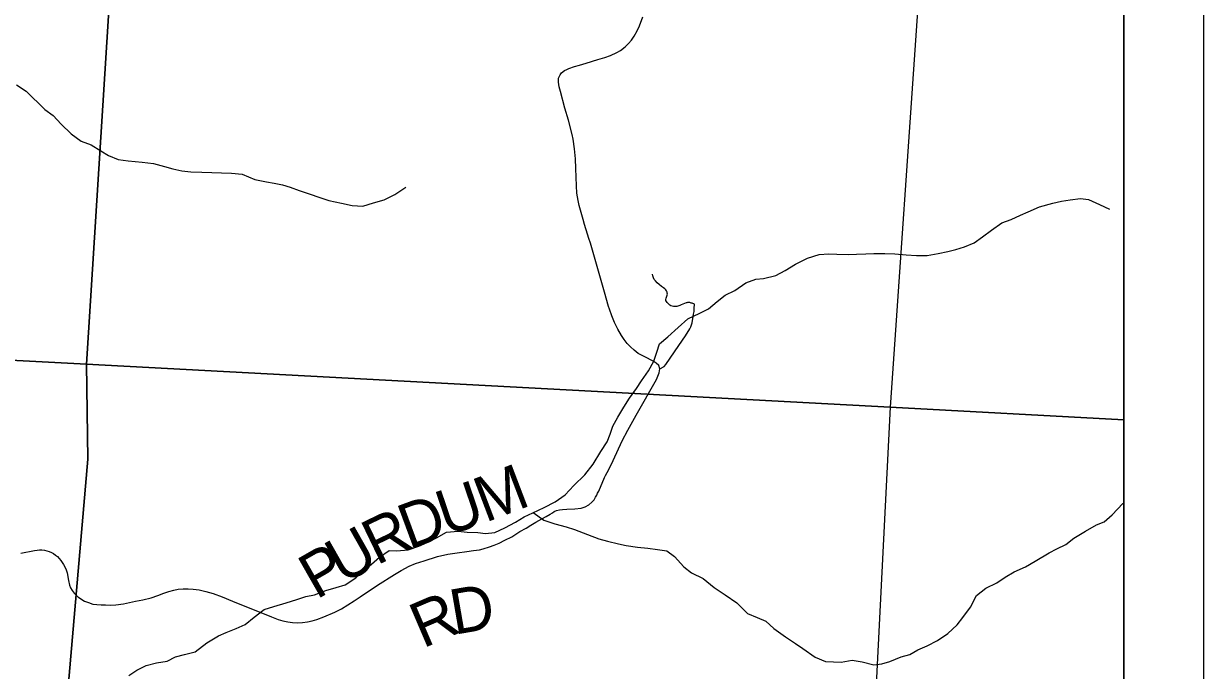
# Model space of a CAD drawing. Extents: x 0 to 34, y 0 to 22.
# Drawn here: x 7.515 to 9, y 19.373 to 20.186 of the extents above; entities that cross this region are included whole.
import ezdxf

# ---------------------------------------------------------------- set-up
doc = ezdxf.new("R2010")
doc.units = 0
for name, color, linetype in [('GM_X_Corporation', 7, 'Continuous'), ('GM_X_Minor_River', 7, 'Continuous'), ('GM_X_Township_Road', 7, 'Continuous'), ('GM_X_Township_Road_Text', 7, 'Continuous'), ('SH_Data', 7, 'Continuous')]:
    doc.layers.add(name, color=color, linetype=linetype)

msp = doc.modelspace()

# ---------------------------------------------------------------- linework, layer by layer
at = {"layer": 'GM_X_Corporation'}
for points in [[(8.9, 18.631), (8.9, 20.9), (3.6477, 20.9), (3.6464, 20.8827), (3.5665, 19.797), (3.566, 19.7906), (3.507, 18.9883), (4.2931, 18.935), (4.421, 18.9263), (4.4362, 18.9253), (5.6003, 18.8464), (6.4706, 18.7873), (6.895, 18.7585), (7.0255, 18.7497), (7.0714, 18.7466), (7.0845, 18.7457), (7.389, 18.725), (7.8088, 18.6965), (7.8353, 18.6952)], [(6.6504, 20.8365), (7.0809, 20.8104), (7.4778, 20.7864), (7.6585, 20.7741), (7.5941, 19.7583), (6.5798, 19.8114)], [(7.6585, 20.7741), (7.6694, 20.7734), (7.9043, 20.7591), (8.3791, 20.7303), (8.6754, 20.7122), (8.6057, 19.704), (7.5941, 19.7583)], [(8.9, 19.6882), (8.9, 20.7033), (8.8781, 20.705), (8.6754, 20.7122), (8.6057, 19.704)], [(6.5798, 19.8114), (7.5941, 19.7583), (7.5958, 19.6386), (7.5162, 18.7157), (6.5391, 18.7835)], [(7.5941, 19.7583), (8.6057, 19.704), (8.5526, 18.6497), (7.5162, 18.7157), (7.5958, 19.6386)], [(8.9, 18.6277), (8.9, 19.6882), (8.6057, 19.704), (8.5526, 18.6497)]]:
    msp.add_lwpolyline(points, close=True, dxfattribs=at)
at = {"layer": 'GM_X_Minor_River'}
for p, q in [((7.506, 20.1094), (7.5181, 20.1015)), ((7.5181, 20.1015), (7.5418, 20.0783)), ((7.5418, 20.0783), (7.5521, 20.0708)), ((7.5521, 20.0708), (7.5624, 20.0599)), ((7.5624, 20.0599), (7.575, 20.0479)), ((7.575, 20.0479), (7.5875, 20.0385)), ((7.5875, 20.0385), (7.6001, 20.0337)), ((7.6001, 20.0337), (7.6122, 20.0262)), ((7.6122, 20.0262), (7.6218, 20.0203)), ((7.6218, 20.0203), (7.6339, 20.0155)), ((7.6339, 20.0155), (7.6468, 20.0137)), ((7.6468, 20.0137), (7.6642, 20.0119)), ((7.6642, 20.0119), (7.6786, 20.0106)), ((7.6786, 20.0106), (7.6926, 20.0065)), ((7.6926, 20.0065), (7.7029, 20.0036)), ((7.7029, 20.0036), (7.7143, 20.001)), ((7.7143, 20.001), (7.7256, 20)), ((7.7256, 20), (7.7392, 19.9994)), ((7.7392, 19.9994), (7.7521, 19.9991)), ((7.7521, 19.9991), (7.7642, 19.9985)), ((7.7642, 19.9985), (7.7767, 19.9982)), ((7.7767, 19.9982), (7.79, 19.9972)), ((7.79, 19.9972), (7.8059, 19.9905)), ((7.8059, 19.9905), (7.8207, 19.9872)), ((7.8207, 19.9872), (7.8306, 19.9858)), ((7.8306, 19.9858), (7.8408, 19.9836)), ((7.8408, 19.9836), (7.8507, 19.9807)), ((7.8507, 19.9807), (7.862, 19.9766)), ((7.862, 19.9766), (7.8757, 19.9718)), ((7.9824, 19.9716), (7.996, 19.9805)), ((7.8757, 19.9718), (7.8867, 19.9681)), ((7.8867, 19.9681), (7.8992, 19.9637)), ((7.8992, 19.9637), (7.9152, 19.9604)), ((7.9152, 19.9604), (7.9288, 19.9575)), ((7.9288, 19.9575), (7.9421, 19.9569)), ((7.9421, 19.9569), (7.9556, 19.9608)), ((7.9556, 19.9608), (7.9688, 19.9647)), ((7.9688, 19.9647), (7.9824, 19.9716)), ((8.1566, 19.5715), (8.1699, 19.5618)), ((8.8853, 19.5687), (8.8984, 19.5829)), ((8.8984, 19.5829), (8.9, 19.5839)), ((8.1699, 19.5618), (8.1839, 19.5574)), ((8.1839, 19.5574), (8.198, 19.5534)), ((8.8654, 19.556), (8.8752, 19.5599)), ((8.8752, 19.5599), (8.8853, 19.5687)), ((8.198, 19.5534), (8.2086, 19.55)), ((8.2086, 19.55), (8.2249, 19.5438)), ((8.2249, 19.5438), (8.2389, 19.5386)), ((8.8371, 19.5391), (8.8518, 19.548)), ((8.8518, 19.548), (8.8654, 19.556)), ((8.2389, 19.5386), (8.2499, 19.5356)), ((8.2499, 19.5356), (8.264, 19.532)), ((8.264, 19.532), (8.2734, 19.5302)), ((8.2734, 19.5302), (8.2878, 19.528)), ((8.2878, 19.528), (8.3007, 19.5266)), ((8.8157, 19.526), (8.827, 19.5314)), ((8.827, 19.5314), (8.8371, 19.5391)), ((8.3007, 19.5266), (8.3128, 19.5252)), ((8.3128, 19.5252), (8.3246, 19.5234)), ((8.3246, 19.5234), (8.3341, 19.5163)), ((8.3341, 19.5163), (8.346, 19.5032)), ((8.7882, 19.5102), (8.8059, 19.521)), ((8.8059, 19.521), (8.8157, 19.526)), ((8.346, 19.5032), (8.3555, 19.4957)), ((8.7618, 19.4971), (8.7762, 19.5033)), ((8.7762, 19.5033), (8.7882, 19.5102)), ((8.3555, 19.4957), (8.3703, 19.4886)), ((8.3703, 19.4886), (8.3844, 19.4774)), ((8.7261, 19.4763), (8.74, 19.4833)), ((8.74, 19.4833), (8.7505, 19.4902)), ((8.7505, 19.4902), (8.7618, 19.4971)), ((8.3844, 19.4774), (8.3981, 19.468)), ((8.3981, 19.468), (8.4129, 19.4579)), ((8.7144, 19.4671), (8.7261, 19.4763)), ((8.4129, 19.4579), (8.4263, 19.4444)), ((8.6973, 19.4397), (8.707, 19.4527)), ((8.707, 19.4527), (8.7144, 19.4671)), ((8.4263, 19.4444), (8.4385, 19.4396)), ((8.4385, 19.4396), (8.4491, 19.4351)), ((8.6902, 19.4301), (8.6973, 19.4397)), ((8.4491, 19.4351), (8.4594, 19.4258)), ((8.4594, 19.4258), (8.4742, 19.4153)), ((8.6785, 19.4194), (8.6902, 19.4301)), ((8.4742, 19.4153), (8.4864, 19.4067)), ((8.6522, 19.4037), (8.6654, 19.4106)), ((8.6654, 19.4106), (8.6785, 19.4194)), ((8.4864, 19.4067), (8.4959, 19.4007)), ((8.4959, 19.4007), (8.5115, 19.3895)), ((8.6303, 19.3932), (8.6405, 19.399)), ((8.6405, 19.399), (8.6522, 19.4037)), ((8.5115, 19.3895), (8.5244, 19.3843)), ((8.5244, 19.3843), (8.5343, 19.3836)), ((8.5343, 19.3836), (8.5441, 19.3833)), ((8.5441, 19.3833), (8.5581, 19.3857)), ((8.5581, 19.3857), (8.5706, 19.3836)), ((8.5706, 19.3836), (8.585, 19.3799)), ((8.585, 19.3799), (8.5952, 19.3812)), ((8.5952, 19.3812), (8.6054, 19.3843)), ((8.6054, 19.3843), (8.6194, 19.3901)), ((8.6194, 19.3901), (8.6303, 19.3932))]:
    msp.add_line(p, q, dxfattribs=at)
for points in [[(8.666, 19.8972), (8.6785, 19.8999), (8.6883, 19.9023), (8.6993, 19.9058), (8.7113, 19.9108), (8.7219, 19.9181), (8.7331, 19.9266), (8.7463, 19.9358), (8.758, 19.9401), (8.7697, 19.9455), (8.7795, 19.9497), (8.7938, 19.9559), (8.8104, 19.9606), (8.8213, 19.963), (8.8323, 19.9646), (8.8455, 19.9663), (8.8554, 19.9652), (8.8691, 19.9589), (8.882, 19.9529)], [(7.6475, 19.3668), (7.6577, 19.3734), (7.6693, 19.3791), (7.6822, 19.3827), (7.6958, 19.3847), (7.7063, 19.3901), (7.7177, 19.3932), (7.7309, 19.3964), (7.7455, 19.4075), (7.7602, 19.4164), (7.77, 19.4206), (7.7828, 19.4257), (7.7938, 19.4307), (7.8054, 19.4399), (7.8178, 19.4495), (7.8299, 19.4534), (7.8454, 19.4581), (7.859, 19.462), (7.8703, 19.4659), (7.8812, 19.4679), (7.8956, 19.4733), (7.9084, 19.4772), (7.9197, 19.4807), (7.9333, 19.4896), (7.943, 19.4984), (7.9528, 19.5064), (7.9629, 19.5152), (7.975, 19.5237), (7.9848, 19.5234), (7.9992, 19.5246), (8.0124, 19.5293), (8.0229, 19.534), (8.0346, 19.5397), (8.0474, 19.5467), (8.0622, 19.5483), (8.0735, 19.5469), (8.0868, 19.5463), (8.0966, 19.5452), (8.108, 19.5465), (8.1208, 19.5523), (8.1343, 19.5596), (8.1452, 19.5661), (8.1558, 19.5712), (8.1701, 19.5777), (8.1841, 19.5851), (8.1968, 19.5939), (8.2077, 19.6057), (8.2216, 19.6188), (8.2321, 19.6325), (8.2418, 19.6481), (8.2496, 19.6603), (8.2533, 19.6702), (8.2566, 19.6801), (8.263, 19.6915), (8.2704, 19.7041), (8.2775, 19.7155), (8.2865, 19.7277), (8.2928, 19.7373), (8.3014, 19.7495), (8.3085, 19.7617), (8.3122, 19.7731), (8.3155, 19.7837), (8.326, 19.7925), (8.3388, 19.804), (8.3512, 19.8151), (8.3663, 19.8224), (8.3772, 19.8275), (8.3881, 19.8367), (8.3982, 19.8447), (8.4103, 19.8509), (8.4242, 19.8605), (8.4366, 19.8651), (8.4465, 19.866), (8.462, 19.8695), (8.4736, 19.8757), (8.4868, 19.8838), (8.5015, 19.8915), (8.5162, 19.8958), (8.5287, 19.8967), (8.5385, 19.8964), (8.5537, 19.8958), (8.5635, 19.8966), (8.5752, 19.8967), (8.5854, 19.8972), (8.5991, 19.8973), (8.6116, 19.8967), (8.6259, 19.8957), (8.6388, 19.8946), (8.6524, 19.8948), (8.666, 19.8972)]]:
    msp.add_lwpolyline(points, dxfattribs=at)
at = {"layer": 'GM_X_Township_Road'}
for points in [[(7.5834, 19.4657), (7.5841, 19.4651), (7.5871, 19.4629), (7.5916, 19.4601), (7.5966, 19.4582), (7.6023, 19.4565), (7.6071, 19.4557), (7.6127, 19.4554), (7.6182, 19.4553), (7.625, 19.4551), (7.6313, 19.4555), (7.6406, 19.4566), (7.656, 19.46), (7.6653, 19.4617), (7.6756, 19.4642), (7.6841, 19.4671), (7.6917, 19.4701), (7.6978, 19.4723), (7.7043, 19.4741), (7.7097, 19.4752), (7.7158, 19.4756), (7.7222, 19.4757), (7.7284, 19.4753), (7.736, 19.4743), (7.7446, 19.4722), (7.7536, 19.4696), (7.7648, 19.4657), (7.7781, 19.4602), (7.8269, 19.4405), (7.8356, 19.4371), (7.8415, 19.4352), (7.8476, 19.4339), (7.8537, 19.4331), (7.8599, 19.4328), (7.8661, 19.4332), (7.8723, 19.4341), (7.8783, 19.4355), (7.8843, 19.4372), (7.893, 19.4404), (7.9069, 19.4464), (7.9152, 19.4506), (7.9232, 19.4554), (7.931, 19.4604), (7.9386, 19.4657), (7.9603, 19.4801), (7.982, 19.4936), (7.9904, 19.4986), (8.0004, 19.5041), (8.0082, 19.5074), (8.0191, 19.5108), (8.036, 19.5161), (8.0492, 19.5191), (8.0609, 19.5209), (8.0729, 19.5224), (8.0812, 19.5236), (8.0887, 19.5247), (8.0937, 19.5259), (8.1013, 19.5282), (8.1075, 19.5304), (8.1137, 19.5332), (8.1209, 19.5366), (8.1297, 19.5411), (8.1398, 19.5475), (8.1476, 19.552), (8.1535, 19.5557), (8.1598, 19.5592), (8.1673, 19.5636), (8.1729, 19.5667), (8.1779, 19.5696), (8.1806, 19.5712), (8.183, 19.5728), (8.1858, 19.5741), (8.1894, 19.5748), (8.1935, 19.5753), (8.1986, 19.5757), (8.2089, 19.5761), (8.2168, 19.5772), (8.2218, 19.5787), (8.2264, 19.5812), (8.2304, 19.5846), (8.233, 19.5876), (8.2349, 19.5908), (8.2364, 19.5935), (8.2374, 19.5959), (8.2389, 19.5986), (8.2462, 19.6154), (8.2474, 19.6182), (8.2517, 19.6258), (8.2571, 19.6368), (8.2686, 19.6618), (8.2754, 19.6753), (8.2862, 19.6941), (8.3117, 19.7389), (8.3151, 19.7472), (8.316, 19.7524), (8.3145, 19.7564), (8.3111, 19.7595), (8.3075, 19.7618), (8.3042, 19.7636), (8.3004, 19.7657), (8.2884, 19.7717), (8.2834, 19.7755), (8.2789, 19.7797), (8.2747, 19.7842), (8.2709, 19.789), (8.2674, 19.7942), (8.2629, 19.8022), (8.2589, 19.8105), (8.2554, 19.819), (8.2526, 19.8271), (8.2514, 19.8307), (8.2461, 19.8486), (8.2285, 19.9101), (8.2266, 19.916), (8.2246, 19.9217), (8.2209, 19.9339), (8.2194, 19.9399), (8.2142, 19.9578), (8.2129, 19.9638), (8.2115, 19.973), (8.2109, 19.9822), (8.2102, 20.004), (8.2096, 20.0164), (8.2085, 20.0288), (8.2066, 20.0411), (8.2054, 20.0471), (8.2007, 20.065), (8.1964, 20.0798), (8.1908, 20.1008), (8.1892, 20.1068), (8.1886, 20.1099), (8.1883, 20.1129), (8.1884, 20.1161), (8.1885, 20.1178), (8.1891, 20.1193), (8.1902, 20.1218), (8.1913, 20.1233), (8.1922, 20.1245), (8.1959, 20.1273), (8.1986, 20.1288), (8.2015, 20.1298), (8.2085, 20.1324), (8.2146, 20.1342), (8.223, 20.1365), (8.2377, 20.141), (8.2468, 20.1438), (8.2537, 20.1464), (8.2616, 20.1499), (8.2664, 20.1525), (8.2723, 20.157), (8.2763, 20.1614), (8.2801, 20.1657), (8.2837, 20.1705), (8.2873, 20.1771), (8.2903, 20.1837), (8.2944, 20.1949)], [(8.3253, 19.8461), (8.3252, 19.8475), (8.3249, 19.8488), (8.3244, 19.8501), (8.3234, 19.8514), (8.3222, 19.8527), (8.3203, 19.8542), (8.3179, 19.8559), (8.3149, 19.8581), (8.3124, 19.8604), (8.3104, 19.8627), (8.3089, 19.8646), (8.3077, 19.8666), (8.3069, 19.869), (8.3065, 19.8714)], [(8.316, 19.7524), (8.3213, 19.755), (8.3236, 19.7577), (8.3396, 19.7814), (8.348, 19.7937), (8.3535, 19.8024), (8.3547, 19.805), (8.3557, 19.8075), (8.3564, 19.8102), (8.357, 19.8131), (8.3574, 19.8153), (8.3584, 19.8208), (8.3589, 19.8244), (8.3591, 19.8279), (8.3593, 19.8336), (8.3565, 19.8346), (8.3553, 19.835), (8.3543, 19.8353), (8.3534, 19.8355), (8.3527, 19.8356), (8.3519, 19.8356), (8.3514, 19.8356), (8.3505, 19.8356), (8.3497, 19.8354), (8.3489, 19.8351), (8.3471, 19.8345), (8.3425, 19.8327), (8.3409, 19.832), (8.3386, 19.8311), (8.3372, 19.8308), (8.3359, 19.8307), (8.3345, 19.8306), (8.333, 19.8307), (8.3314, 19.831), (8.3298, 19.8314), (8.3283, 19.8324), (8.3266, 19.834), (8.3249, 19.8357), (8.3242, 19.8367), (8.3236, 19.838), (8.3236, 19.8393), (8.324, 19.8409), (8.3252, 19.8447), (8.3253, 19.8461)], [(7.5115, 19.5205), (7.5289, 19.5238), (7.532, 19.5243), (7.5351, 19.5245), (7.5382, 19.5245), (7.5413, 19.5241), (7.5443, 19.5234), (7.5473, 19.5225), (7.5501, 19.5213), (7.5528, 19.5198), (7.5554, 19.5181), (7.5578, 19.5161), (7.5599, 19.5138), (7.5618, 19.5114), (7.5651, 19.5061), (7.5682, 19.5009), (7.5698, 19.4958), (7.5717, 19.4861), (7.573, 19.4803), (7.5742, 19.477), (7.5761, 19.4733), (7.5787, 19.4703), (7.5811, 19.4677), (7.5834, 19.4657)]]:
    msp.add_lwpolyline(points, dxfattribs=at)
at = {"layer": 'SH_Data'}
for p, q in [((9, 21), (9, 14)), ((8.9, 20.9), (8.9, 14.1))]:
    msp.add_line(p, q, dxfattribs=at)

# ---------------------------------------------------------------- texts
at = {"layer": 'GM_X_Township_Road_Text'}
for s, rotation, p in [('M', 20.8873, (8.0961, 19.5585)), ('U', 18.7379, (8.0466, 19.5416)), ('D', 20.3267, (8.0001, 19.5244)), ('R', 25.7587, (7.9594, 19.5047)), ('U', 29.5217, (7.9168, 19.4805)), ('P', 29.7455, (7.8835, 19.4615)), ('R', 23.1945, (8.0175, 19.4003)), ('D', 9.8516, (8.0571, 19.4177))]:
    msp.add_text(s, height=0.0568, rotation=rotation, dxfattribs=at).set_placement(p)

doc.saveas('drawing.dxf')
